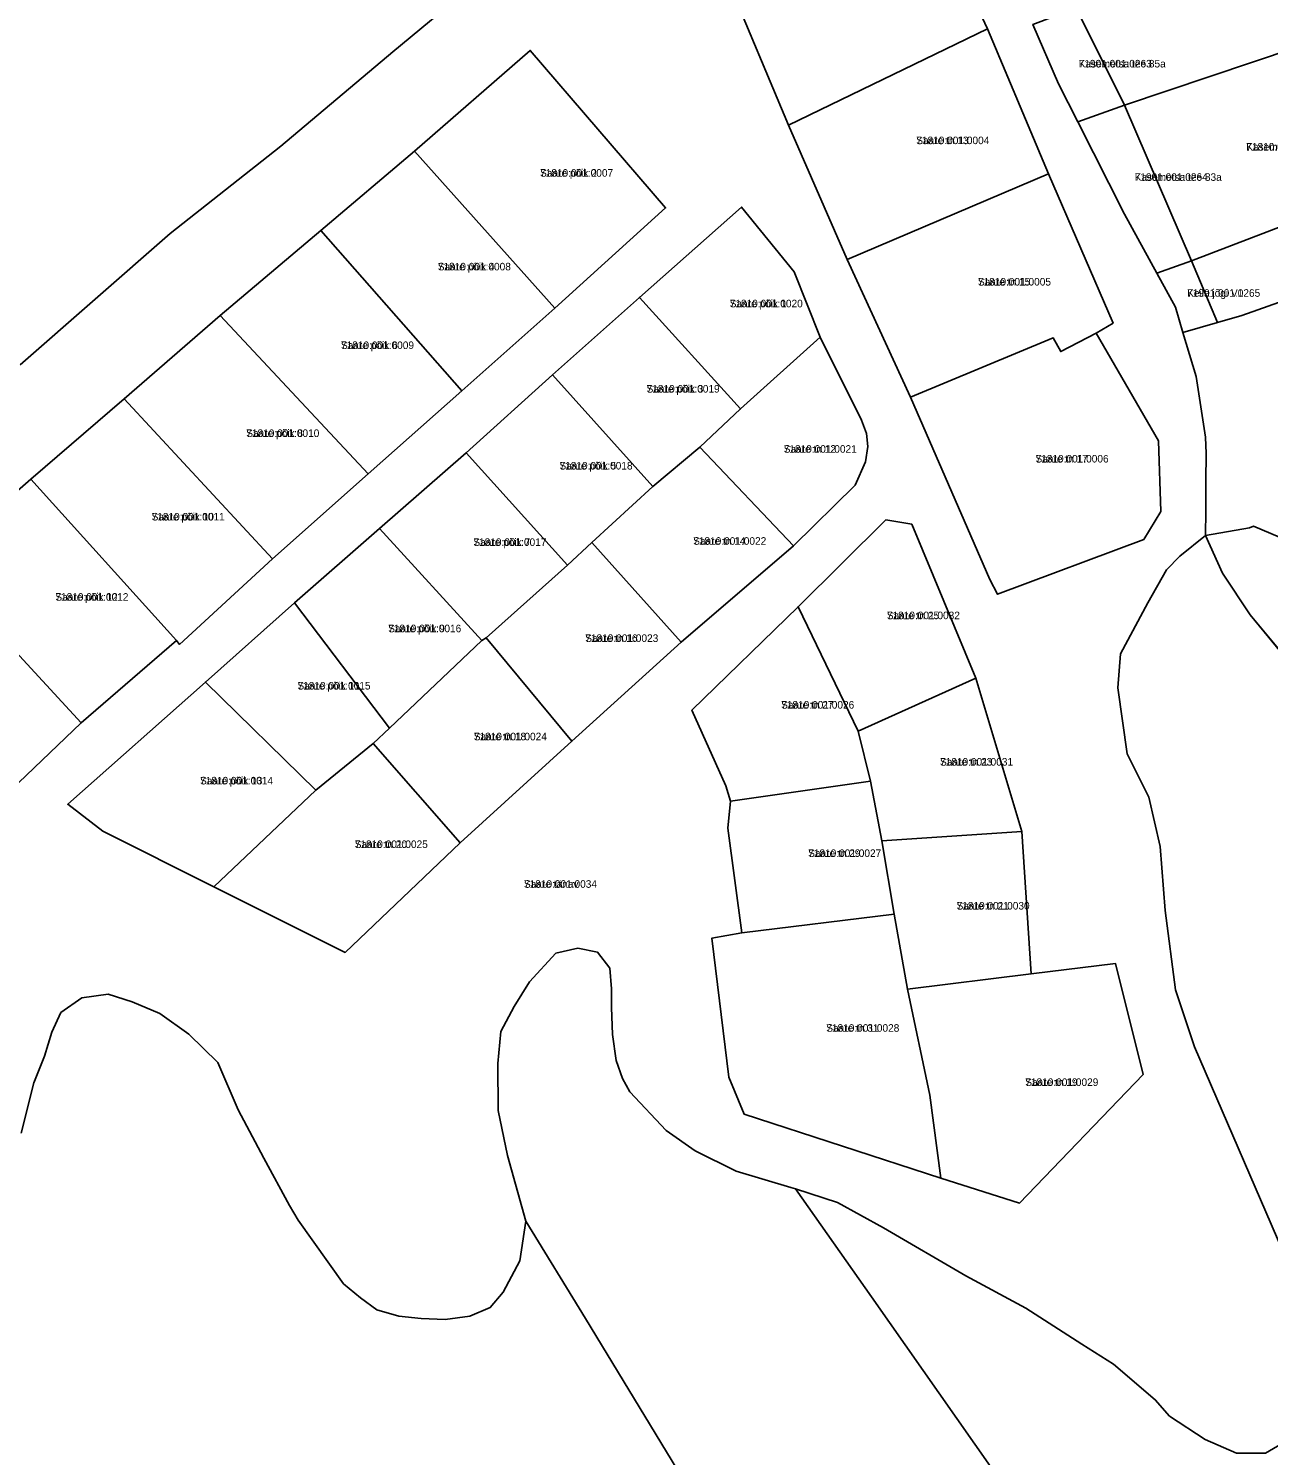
# Model space of a CAD drawing. Extents: x 529768 to 552006, y 6562269 to 6580975.
# Drawn here: x 537630.1 to 537876.3, y 6567066.6 to 6567349.9 of the extents above; entities that cross this region are included whole.
import ezdxf

# ---------------------------------------------------------------- set-up
doc = ezdxf.new("R2010")
doc.units = 0
for name, color, linetype in [('L_AADRESS', 7, 'Continuous'), ('PIIR', 7, 'Continuous'), ('TUNNUS', 7, 'Continuous')]:
    doc.layers.add(name, color=color, linetype=linetype)

msp = doc.modelspace()

# ---------------------------------------------------------------- linework, layer by layer
at = {"layer": 'PIIR'}
for points in [[(537779.57, 6567441.53), (537770.69, 6567434.81), (537764.72, 6567428.52), (537760.05, 6567419.87), (537757.98, 6567408.72), (537757.76, 6567405.8), (537760.54, 6567392.24), (537764.13, 6567374.73), (537768.91, 6567359.61), (537781, 6567330.64), (537792.65, 6567304.01), (537805.22, 6567276.68), (537821, 6567240.45), (537822.49, 6567237.53), (537851.52, 6567248.43), (537854.89, 6567253.96), (537854.48, 6567267.98), (537842.1, 6567289.36), (537845.43, 6567291.37), (537832.59, 6567320.98), (537820.5, 6567349.78), (537808.28, 6567375.94), (537798.06, 6567399.32)], [(537820.5, 6567349.78), (537781, 6567330.64), (537768.91, 6567359.61), (537808.28, 6567375.94)], [(537873.03, 6567365.29), (537881.62, 6567346.03), (537847.69, 6567334.61), (537838.09, 6567353.89)], [(537834.6, 6567338.85), (537829.52, 6567350.66), (537838.09, 6567353.89), (537847.69, 6567334.61), (537838.42, 6567331.33)], [(537832.59, 6567320.98), (537792.65, 6567304.01), (537781, 6567330.64), (537820.5, 6567349.78)], [(537881.62, 6567346.03), (537888.38, 6567347.48), (537895.98, 6567331.66), (537895.07, 6567330.21), (537883.94, 6567312.55), (537861.04, 6567303.76), (537847.69, 6567334.61)], [(537729.73, 6567345.5), (537706.74, 6567325.5), (537688.15, 6567309.75), (537668.14, 6567292.87), (537649.12, 6567276.37), (537630.55, 6567260.4), (537611.37, 6567243.65), (537590.02, 6567224.75), (537615.59, 6567188.18), (537640.54, 6567212), (537659.53, 6567228.39), (537660.1, 6567227.6), (537678.57, 6567244.59), (537697.58, 6567261.46), (537716.16, 6567277.94), (537734.62, 6567294.36), (537756.61, 6567314.24)], [(537756.61, 6567314.24), (537734.62, 6567294.36), (537706.74, 6567325.5), (537729.73, 6567345.5)], [(537847.72, 6567313.03), (537838.42, 6567331.33), (537847.69, 6567334.61), (537861.04, 6567303.76), (537854.11, 6567301.31)], [(537734.62, 6567294.36), (537716.16, 6567277.94), (537688.15, 6567309.75), (537706.74, 6567325.5)], [(537845.43, 6567291.37), (537842.1, 6567289.36), (537835.04, 6567285.71), (537833.53, 6567288.47), (537805.22, 6567276.68), (537792.65, 6567304.01), (537832.59, 6567320.98)], [(537771.7, 6567314.4), (537751.4, 6567296.47), (537734.16, 6567281.09), (537717.03, 6567265.64), (537699.78, 6567250.57), (537682.92, 6567235.81), (537665.24, 6567220.11), (537637.92, 6567195.87), (537644.88, 6567190.48), (537666.93, 6567179.46), (537693.01, 6567166.43), (537715.8, 6567188.18), (537738.01, 6567208.36), (537759.68, 6567228), (537782, 6567247.16), (537794.23, 6567259.19), (537796.26, 6567263.85), (537796.72, 6567266.85), (537796.47, 6567269.47), (537795.5, 6567272.12), (537787.26, 6567288.6), (537782.15, 6567301.53)], [(537782.15, 6567301.53), (537787.26, 6567288.6), (537771.5, 6567274.33), (537751.4, 6567296.47), (537771.7, 6567314.4)], [(537716.16, 6567277.94), (537697.58, 6567261.46), (537668.14, 6567292.87), (537688.15, 6567309.75)], [(537854.11, 6567301.31), (537861.04, 6567303.76), (537866.19, 6567291.51), (537859.31, 6567289.51), (537857.8, 6567294.55)], [(537771.5, 6567274.33), (537763.39, 6567266.74), (537754.04, 6567258.91), (537734.16, 6567281.09), (537751.4, 6567296.47)], [(537859.31, 6567289.51), (537866.19, 6567291.51), (537870.98, 6567292.91), (537887.82, 6567298.82), (537902.8, 6567293.01), (537894.52, 6567254.78), (537890.99, 6567243.57), (537873.33, 6567251.07), (537872.55, 6567250.74), (537863.78, 6567249.19), (537863.88, 6567254.13), (537863.88, 6567259.97), (537863.93, 6567265.48), (537863.81, 6567268.74), (537861.92, 6567280.8)], [(537697.58, 6567261.46), (537678.57, 6567244.59), (537649.12, 6567276.37), (537668.14, 6567292.87)], [(537795.5, 6567272.12), (537796.47, 6567269.47), (537796.72, 6567266.85), (537796.26, 6567263.85), (537794.23, 6567259.19), (537782, 6567247.16), (537763.39, 6567266.74), (537771.5, 6567274.33), (537787.26, 6567288.6)], [(537854.48, 6567267.98), (537854.89, 6567253.96), (537851.52, 6567248.43), (537822.49, 6567237.53), (537821, 6567240.45), (537805.22, 6567276.68), (537833.53, 6567288.47), (537835.04, 6567285.71), (537842.1, 6567289.36)], [(537754.04, 6567258.91), (537741.97, 6567247.8), (537737.1, 6567243.32), (537717.03, 6567265.64), (537734.16, 6567281.09)], [(537678.57, 6567244.59), (537660.1, 6567227.6), (537659.53, 6567228.39), (537630.55, 6567260.4), (537649.12, 6567276.37)], [(537737.1, 6567243.32), (537721, 6567228.92), (537720.14, 6567228.36), (537699.78, 6567250.57), (537717.03, 6567265.64)], [(537782, 6567247.16), (537759.68, 6567228), (537741.97, 6567247.8), (537754.04, 6567258.91), (537763.39, 6567266.74)], [(537659.53, 6567228.39), (537640.54, 6567212), (537611.37, 6567243.65), (537630.55, 6567260.4)], [(537800.34, 6567252.29), (537782.89, 6567235.05), (537761.81, 6567214.51), (537768.58, 6567199.52), (537769.48, 6567196.46), (537768.96, 6567191.13), (537771.73, 6567170.35), (537765.75, 6567169.25), (537769.18, 6567141.64), (537772.18, 6567134.32), (537811.26, 6567121.61), (537826.89, 6567116.68), (537851.41, 6567142.2), (537845.95, 6567164.23), (537829.18, 6567162.16), (537827.34, 6567190.45), (537818.17, 6567220.87), (537805.48, 6567251.44)], [(537805.48, 6567251.44), (537818.17, 6567220.87), (537794.82, 6567210.36), (537782.89, 6567235.05), (537800.34, 6567252.29)], [(537863.78, 6567249.19), (537872.55, 6567250.74), (537873.33, 6567251.07), (537890.99, 6567243.57), (537878.25, 6567226.68), (537872.68, 6567233.45), (537867.16, 6567241.71)], [(537720.14, 6567228.36), (537701.79, 6567210.99), (537682.92, 6567235.81), (537699.78, 6567250.57)], [(537759.68, 6567228), (537738.01, 6567208.36), (537721, 6567228.92), (537737.1, 6567243.32), (537741.97, 6567247.8)], [(537640.54, 6567212), (537615.59, 6567188.18), (537590.02, 6567224.75), (537611.37, 6567243.65)], [(537701.79, 6567210.99), (537698.52, 6567207.91), (537687.15, 6567198.67), (537665.24, 6567220.11), (537682.92, 6567235.81)], [(537794.82, 6567210.36), (537797.28, 6567200.43), (537769.48, 6567196.46), (537768.58, 6567199.52), (537761.81, 6567214.51), (537782.89, 6567235.05)], [(537738.01, 6567208.36), (537715.8, 6567188.18), (537698.52, 6567207.91), (537701.79, 6567210.99), (537720.14, 6567228.36), (537721, 6567228.92)], [(537687.15, 6567198.67), (537666.93, 6567179.46), (537644.88, 6567190.48), (537637.92, 6567195.87), (537665.24, 6567220.11)], [(537827.34, 6567190.45), (537799.56, 6567188.59), (537797.28, 6567200.43), (537794.82, 6567210.36), (537818.17, 6567220.87)], [(537715.8, 6567188.18), (537693.01, 6567166.43), (537666.93, 6567179.46), (537687.15, 6567198.67), (537698.52, 6567207.91)], [(537799.56, 6567188.59), (537802.01, 6567174), (537771.73, 6567170.35), (537768.96, 6567191.13), (537769.48, 6567196.46), (537797.28, 6567200.43)], [(537829.18, 6567162.16), (537804.62, 6567159.11), (537802.01, 6567174), (537799.56, 6567188.59), (537827.34, 6567190.45)], [(537804.62, 6567159.11), (537809.09, 6567138.07), (537811.26, 6567121.61), (537772.18, 6567134.32), (537769.18, 6567141.64), (537765.75, 6567169.25), (537771.73, 6567170.35), (537802.01, 6567174)], [(537851.41, 6567142.2), (537826.89, 6567116.68), (537811.26, 6567121.61), (537809.09, 6567138.07), (537804.62, 6567159.11), (537829.18, 6567162.16), (537845.95, 6567164.23)]]:
    msp.add_lwpolyline(points, close=True, dxfattribs=at)
for points in [[(537627.29, 6567437.78), (537644.47, 6567432.37), (537661.34, 6567427.59), (537669.61, 6567425.36), (537678.52, 6567422.81), (537688.39, 6567417.4), (537695.71, 6567410.71), (537703.98, 6567404.98), (537711.3, 6567400.53), (537723.4, 6567392.88), (537727.85, 6567389.06), (537729.76, 6567384.61), (537730.71, 6567377.61), (537729.93, 6567369.41), (537727.43, 6567365.95), (537723.17, 6567362.15), (537718.93, 6567358.92), (537702.43, 6567345.21), (537680.18, 6567326.48), (537658.23, 6567309.19), (537628.46, 6567283.1)], [(537628.46, 6567283.1), (537658.23, 6567309.19), (537680.18, 6567326.48), (537702.43, 6567345.21), (537718.93, 6567358.92), (537723.17, 6567362.15), (537727.43, 6567365.95), (537729.93, 6567369.41), (537730.71, 6567377.61), (537729.76, 6567384.61), (537727.85, 6567389.06), (537723.4, 6567392.88), (537711.3, 6567400.53), (537703.98, 6567404.98), (537695.71, 6567410.71), (537688.39, 6567417.4), (537678.52, 6567422.81), (537669.61, 6567425.36), (537661.34, 6567427.59), (537644.47, 6567432.37), (537627.29, 6567437.78)], [(537829.52, 6567350.66), (537834.6, 6567338.85), (537838.42, 6567331.33), (537847.72, 6567313.03), (537854.11, 6567301.31), (537857.8, 6567294.55), (537859.31, 6567289.51), (537861.92, 6567280.8), (537863.81, 6567268.74), (537863.93, 6567265.48), (537863.88, 6567259.97), (537863.88, 6567254.13), (537863.78, 6567249.19), (537858.71, 6567245.1), (537856.06, 6567242.42), (537852.34, 6567235.84), (537846.89, 6567225.72), (537846.37, 6567218.99), (537848.21, 6567205.88), (537852.53, 6567197.29), (537854.78, 6567187.46), (537855.79, 6567174.78), (537857.81, 6567159.02), (537861.6, 6567147.72), (537880.18, 6567104.69)], [(537887.82, 6567298.82), (537870.98, 6567292.91), (537866.19, 6567291.51), (537861.04, 6567303.76), (537883.94, 6567312.55)], [(537880.18, 6567104.69), (537861.6, 6567147.72), (537857.81, 6567159.02), (537855.79, 6567174.78), (537854.78, 6567187.46), (537852.53, 6567197.29), (537848.21, 6567205.88), (537846.37, 6567218.99), (537846.89, 6567225.72), (537852.34, 6567235.84), (537856.06, 6567242.42), (537858.71, 6567245.1), (537863.78, 6567249.19), (537867.16, 6567241.71), (537872.68, 6567233.45), (537879.73, 6567224.88)], [(537878.87, 6567068.88), (537875.68, 6567067.03), (537869.96, 6567067.03), (537863.74, 6567069.72), (537856.65, 6567074.4), (537853.82, 6567077.63), (537845.53, 6567084.72), (537839.22, 6567088.66), (537828.1, 6567095.78), (537816.18, 6567102.26), (537799.88, 6567111.74), (537790.74, 6567116.77), (537782.39, 6567119.49), (537781.48, 6567119.79), (537770.63, 6567123.03), (537762.48, 6567127.07), (537756.68, 6567131.11), (537749.47, 6567138.75), (537748.06, 6567141.44), (537746.76, 6567144.96), (537746.03, 6567150.17), (537745.85, 6567155.48), (537745.85, 6567159.23), (537745.56, 6567163.34), (537743.09, 6567166.47), (537739.16, 6567167.28), (537734.81, 6567166.3), (537729.56, 6567160.6), (537726.56, 6567155.73), (537723.87, 6567150.77), (537723.31, 6567144.38), (537723.37, 6567135.06), (537725.23, 6567126.11), (537728.88, 6567113.09), (537727.67, 6567105.19), (537724.36, 6567098.98), (537721.8, 6567095.97), (537717.71, 6567094.21), (537712.81, 6567093.55), (537708.06, 6567093.73), (537703.66, 6567094.23), (537699.24, 6567095.46), (537696.01, 6567097.84), (537692.62, 6567100.65), (537683.68, 6567113.31), (537681.9, 6567116.19), (537676.84, 6567125.61), (537671.75, 6567135.2), (537667.67, 6567144.59), (537661.93, 6567150.2), (537656.18, 6567154.28), (537650.68, 6567156.66), (537645.91, 6567158.17), (537640.68, 6567157.41), (537636.54, 6567154.49), (537634.75, 6567150.58), (537633.26, 6567145.86), (537631.17, 6567140.53), (537628.65, 6567130.57)], [(537801.85, 6566993.12), (537740.69, 6567093.78), (537728.88, 6567113.09), (537725.23, 6567126.11), (537723.37, 6567135.06), (537723.31, 6567144.38), (537723.87, 6567150.77), (537726.56, 6567155.73), (537729.56, 6567160.6), (537734.81, 6567166.3), (537739.16, 6567167.28), (537743.09, 6567166.47), (537745.56, 6567163.34), (537745.85, 6567159.23), (537745.85, 6567155.48), (537746.03, 6567150.17), (537746.76, 6567144.96), (537748.06, 6567141.44), (537749.47, 6567138.75), (537756.68, 6567131.11), (537762.48, 6567127.07), (537770.63, 6567123.03), (537781.48, 6567119.79), (537782.39, 6567119.49), (537797.51, 6567098.05), (537854.98, 6567016.09)], [(537628.65, 6567130.57), (537631.17, 6567140.53), (537633.26, 6567145.86), (537634.75, 6567150.58), (537636.54, 6567154.49), (537640.68, 6567157.41), (537645.91, 6567158.17), (537650.68, 6567156.66), (537656.18, 6567154.28), (537661.93, 6567150.2), (537667.67, 6567144.59), (537671.75, 6567135.2), (537676.84, 6567125.61), (537681.9, 6567116.19), (537683.68, 6567113.31), (537692.62, 6567100.65), (537696.01, 6567097.84), (537699.24, 6567095.46), (537703.66, 6567094.23), (537708.06, 6567093.73), (537712.81, 6567093.55), (537717.71, 6567094.21), (537721.8, 6567095.97), (537724.36, 6567098.98), (537727.67, 6567105.19), (537728.88, 6567113.09), (537740.69, 6567093.78), (537801.85, 6566993.12)], [(537854.98, 6567016.09), (537797.51, 6567098.05), (537782.39, 6567119.49), (537790.74, 6567116.77), (537799.88, 6567111.74), (537816.18, 6567102.26), (537828.1, 6567095.78), (537839.22, 6567088.66), (537845.53, 6567084.72), (537853.82, 6567077.63), (537856.65, 6567074.4), (537863.74, 6567069.72), (537869.96, 6567067.03), (537875.68, 6567067.03), (537878.87, 6567068.88)]]:
    msp.add_lwpolyline(points, dxfattribs=at)

# ---------------------------------------------------------------- texts
at = {"layer": 'L_AADRESS'}
for s, p in [('Kasemetsa tee 85a', (537838.61, 6567342.13)), ('Saare tn 13', (537806.37, 6567326.9)), ('Kasemetsa tee 83', (537871.88, 6567325.62)), ('Saare põik 2', (537731.68, 6567320.44)), ('Kasemetsa tee 83a', (537849.73, 6567319.62)), ('Saare põik 4', (537711.38, 6567301.84)), ('Saare tn 15', (537818.61, 6567298.83)), ('Keila jõgi V1', (537860.15, 6567296.6)), ('Saare põik 1', (537769.33, 6567294.51)), ('Saare põik 6', (537692.15, 6567286.23)), ('Saare põik 3', (537752.83, 6567277.58)), ('Saare põik 8', (537673.35, 6567268.77)), ('Saare tn 12', (537780.05, 6567265.64)), ('Saare tn 17', (537830.05, 6567263.7)), ('Saare põik 5', (537735.54, 6567262.31)), ('Saare põik 10', (537654.56, 6567252.19)), ('Saare põik 7', (537718.44, 6567247.14)), ('Saare tn 14', (537762.08, 6567247.37)), ('Saare põik 12', (537635.45, 6567236.26)), ('Saare tn 25', (537800.53, 6567232.59)), ('Saare põik 9', (537701.53, 6567230)), ('Saare tn 16', (537740.65, 6567228.08)), ('Saare põik 11', (537683.52, 6567218.63)), ('Saare tn 27', (537779.55, 6567214.84)), ('Saare tn 18', (537718.53, 6567208.55)), ('Saare tn 23', (537811.08, 6567203.52)), ('Saare põik 13', (537664.17, 6567199.79)), ('Saare tn 20', (537694.89, 6567187.17)), ('Saare tn 29', (537784.91, 6567185.39)), ('Saare tänav', (537728.48, 6567179.27)), ('Saare tn 21', (537814.37, 6567174.95)), ('Saare tn 31', (537788.5, 6567150.69)), ('Saare tn 19', (537828.01, 6567139.93))]:
    msp.add_text(s, height=1.5, dxfattribs=at).set_placement(p)
at = {"layer": 'TUNNUS'}
for s, p in [('71901:001:0263', (537838.61, 6567342.13)), ('71810:001:0004', (537806.37, 6567326.9)), ('71810:002:0019', (537871.88, 6567325.62)), ('71810:001:0007', (537731.68, 6567320.44)), ('71901:001:0264', (537849.73, 6567319.62)), ('71810:001:0008', (537711.38, 6567301.84)), ('71810:001:0005', (537818.61, 6567298.83)), ('71901:001:0265', (537860.15, 6567296.6)), ('71810:001:0020', (537769.33, 6567294.51)), ('71810:001:0009', (537692.15, 6567286.23)), ('71810:001:0019', (537752.83, 6567277.58)), ('71810:001:0010', (537673.35, 6567268.77)), ('71810:001:0021', (537780.05, 6567265.64)), ('71810:001:0006', (537830.05, 6567263.7)), ('71810:001:0018', (537735.54, 6567262.31)), ('71810:001:0011', (537654.56, 6567252.19)), ('71810:001:0017', (537718.44, 6567247.14)), ('71810:001:0022', (537762.08, 6567247.37)), ('71810:001:0012', (537635.45, 6567236.26)), ('71810:001:0032', (537800.53, 6567232.59)), ('71810:001:0016', (537701.53, 6567230)), ('71810:001:0023', (537740.65, 6567228.08)), ('71810:001:0015', (537683.52, 6567218.63)), ('71810:001:0026', (537779.55, 6567214.84)), ('71810:001:0024', (537718.53, 6567208.55)), ('71810:001:0031', (537811.08, 6567203.52)), ('71810:001:0014', (537664.17, 6567199.79)), ('71810:001:0025', (537694.89, 6567187.17)), ('71810:001:0027', (537784.91, 6567185.39)), ('71810:001:0034', (537728.48, 6567179.27)), ('71810:001:0030', (537814.37, 6567174.95)), ('71810:001:0028', (537788.5, 6567150.69)), ('71810:001:0029', (537828.01, 6567139.93))]:
    msp.add_text(s, height=1.5, dxfattribs=at).set_placement(p)

doc.saveas('drawing.dxf')
